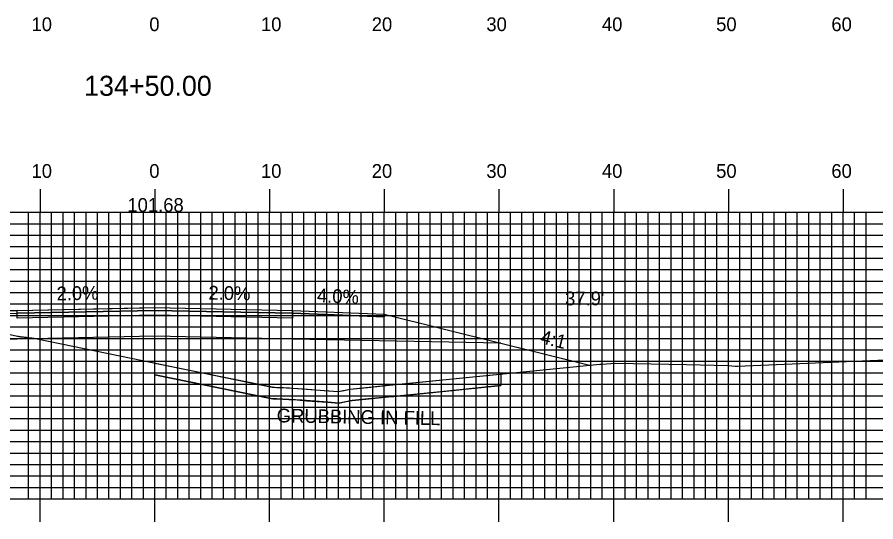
# Model space of a CAD drawing. Extents: x 1774777 to 1775120, y 442591 to 442811.
# Drawn here: x 1774930.7 to 1775005.5, y 442691.7 to 442735.7 of the extents above; entities that cross this region are included whole.
import ezdxf

# ---------------------------------------------------------------- set-up
doc = ezdxf.new("R2010")
doc.units = 0
for name, color, linetype in [('ANNOTATION', 7, 'Continuous'), ('D_Roadway_Centerline', 7, 'Continuous'), ('D_Roadway_Centerline_Text', 7, 'Continuous'), ('D_Roadway_Edge_Shoulder', 7, 'Continuous'), ('D_Roadway_Edge_TW', 7, 'Continuous'), ('D_Roadway_Pavement', 7, 'Continuous'), ('D_Roadway_SlopeLines', 7, 'Continuous'), ('D_Roadway_SubGrade', 7, 'Continuous'), ('D_Text_Standard', 7, 'Continuous'), ('GRUBBING IN FILL', 7, 'Continuous'), ('H_V ANNOTATION', 7, 'Continuous'), ('MAJOR', 7, 'Continuous'), ('MINOR', 7, 'Continuous'), ('S_Roadway_Centerline', 7, 'Continuous')]:
    doc.layers.add(name, color=color, linetype=linetype)

msp = doc.modelspace()

# ---------------------------------------------------------------- linework, layer by layer
at = {"layer": 'D_Roadway_Centerline'}
msp.add_lwpolyline([(1774888.041, 442709.232), (1774889.291, 442709.207), (1774890.427, 442709.137), (1774890.541, 442709.13), (1774890.711, 442709.113), (1774891.791, 442709), (1774892.519, 442708.894), (1774893.041, 442708.818), (1774903.358, 442707.099), (1774908.511, 442706.24), (1774909.434, 442706.471), (1774912.511, 442707.24), (1774916.843, 442708.323), (1774922.685, 442709.784), (1774930.685, 442710.104), (1774941.714, 442710.325), (1774942.685, 442710.344), (1774943.996, 442710.318), (1774954.685, 442710.104), (1774962.685, 442709.784), (1774972.86, 442707.24), (1774975.44, 442706.595), (1774980.561, 442705.315)], dxfattribs=at)
at = {"layer": 'D_Roadway_Edge_Shoulder'}
for points in [[(1774930.685, 442710.104), (1774922.685, 442709.784), (1774922.685, 442709.534), (1774930.685, 442709.854)], [(1774954.685, 442710.104), (1774962.685, 442709.784), (1774962.685, 442709.534), (1774954.685, 442709.854)]]:
    msp.add_lwpolyline(points, close=True, dxfattribs=at)
at = {"layer": 'D_Roadway_Edge_TW'}
msp.add_lwpolyline([(1774930.685, 442709.854), (1774930.685, 442710.104), (1774942.685, 442710.344), (1774954.685, 442710.104), (1774954.685, 442709.854), (1774942.685, 442710.094)], close=True, dxfattribs=at)
at = {"layer": 'D_Roadway_Pavement'}
msp.add_lwpolyline([(1774930.685, 442709.437), (1774930.685, 442709.854), (1774942.685, 442710.094), (1774954.685, 442709.854), (1774954.685, 442709.437), (1774942.685, 442709.677)], close=True, dxfattribs=at)
at = {"layer": 'D_Roadway_SlopeLines'}
msp.add_lwpolyline([(1774962.685, 442709.784), (1774972.86, 442707.24), (1774980.561, 442705.315)], dxfattribs=at)
at = {"layer": 'D_Roadway_SubGrade'}
msp.add_lwpolyline([(1774930.685, 442707.604), (1774912.511, 442707.24), (1774922.685, 442709.784), (1774922.685, 442709.534), (1774930.685, 442709.854), (1774942.685, 442710.094), (1774954.685, 442709.854), (1774962.685, 442709.534), (1774962.685, 442709.784), (1774972.86, 442707.24), (1774954.685, 442707.604), (1774942.685, 442707.844)], close=True, dxfattribs=at)
at = {"layer": 'GRUBBING IN FILL'}
msp.add_line((1774972.86, 442704.545), (1774972.86, 442703.54), dxfattribs=at)
msp.add_line((1774972.86, 442704.545), (1774972.86, 442703.54), dxfattribs=at)
msp.add_lwpolyline([(1774942.685, 442704.493), (1774942.685, 442705.514), (1774953.071, 442703.402), (1774954.719, 442703.319), (1774958.657, 442703.026), (1774959.726, 442703.244), (1774961.501, 442703.422), (1774963.36, 442703.603), (1774972.455, 442704.505), (1774972.86, 442704.545), (1774972.86, 442703.54), (1774968.182, 442703.073), (1774963.505, 442702.606), (1774961.608, 442702.428), (1774959.877, 442702.254), (1774959.048, 442702.085), (1774958.719, 442702.018), (1774957.76, 442702.091), (1774955.513, 442702.26), (1774953.848, 442702.367), (1774952.784, 442702.412)], close=True, dxfattribs=at)
msp.add_lwpolyline([(1774942.685, 442704.493), (1774942.685, 442705.514), (1774953.071, 442703.402), (1774954.719, 442703.319), (1774958.657, 442703.026), (1774959.726, 442703.244), (1774961.501, 442703.422), (1774963.36, 442703.603), (1774972.455, 442704.505), (1774972.86, 442704.545), (1774972.86, 442703.54), (1774968.182, 442703.073), (1774963.505, 442702.606), (1774961.608, 442702.428), (1774959.877, 442702.254), (1774959.048, 442702.085), (1774958.719, 442702.018), (1774957.76, 442702.091), (1774955.513, 442702.26), (1774953.848, 442702.367), (1774952.784, 442702.412)], close=True, dxfattribs=at)
msp.add_lwpolyline([(1774942.685, 442704.493), (1774952.784, 442702.412), (1774952.971, 442702.405), (1774953.094, 442702.4), (1774953.241, 442702.394), (1774953.415, 442702.387), (1774953.617, 442702.378), (1774953.848, 442702.367), (1774954.103, 442702.354), (1774954.367, 442702.339), (1774954.653, 442702.321), (1774955.106, 442702.29), (1774955.92, 442702.23), (1774957.76, 442702.091), (1774958.719, 442702.018), (1774959.376, 442702.151), (1774959.877, 442702.254), (1774963.338, 442702.602), (1774963.505, 442702.606), (1774972.86, 442703.54)], dxfattribs=at)
msp.add_lwpolyline([(1774942.685, 442704.493), (1774952.784, 442702.412), (1774952.971, 442702.405), (1774953.094, 442702.4), (1774953.241, 442702.394), (1774953.415, 442702.387), (1774953.617, 442702.378), (1774953.848, 442702.367), (1774954.103, 442702.354), (1774954.367, 442702.339), (1774954.653, 442702.321), (1774955.106, 442702.29), (1774955.92, 442702.23), (1774957.76, 442702.091), (1774958.719, 442702.018), (1774959.376, 442702.151), (1774959.877, 442702.254), (1774963.338, 442702.602), (1774963.505, 442702.606), (1774972.86, 442703.54)], dxfattribs=at)
at = {"layer": 'MAJOR'}
for p, q in [((1774932.685, 442720.669), (1774932.685, 442718.665)), ((1774942.685, 442720.669), (1774942.685, 442718.665)), ((1774952.685, 442720.669), (1774952.685, 442718.665)), ((1774962.685, 442720.669), (1774962.685, 442718.665)), ((1774972.685, 442720.669), (1774972.685, 442718.665)), ((1774982.685, 442720.669), (1774982.685, 442718.665)), ((1774992.685, 442720.669), (1774992.685, 442718.665)), ((1775002.685, 442720.669), (1775002.685, 442718.665)), ((1774802.685, 442718.665), (1775082.685, 442718.665)), ((1774802.685, 442718.665), (1775082.685, 442718.665)), ((1774932.685, 442693.665), (1774932.685, 442718.665)), ((1774942.685, 442693.665), (1774942.685, 442718.665)), ((1774952.685, 442693.665), (1774952.685, 442718.665)), ((1774962.685, 442693.665), (1774962.685, 442718.665)), ((1774972.685, 442693.665), (1774972.685, 442718.665)), ((1774982.685, 442693.665), (1774982.685, 442718.665)), ((1774992.685, 442693.665), (1774992.685, 442718.665)), ((1775002.685, 442693.665), (1775002.685, 442718.665)), ((1774802.685, 442713.665), (1775082.685, 442713.665)), ((1774802.685, 442708.665), (1775082.685, 442708.665)), ((1774802.685, 442703.665), (1775082.685, 442703.665)), ((1774802.685, 442698.665), (1775082.685, 442698.665)), ((1774802.685, 442693.665), (1775082.685, 442693.665)), ((1774802.685, 442693.665), (1775082.685, 442693.665)), ((1774932.685, 442691.661), (1774932.685, 442693.665)), ((1774942.685, 442691.661), (1774942.685, 442693.665)), ((1774952.685, 442691.661), (1774952.685, 442693.665)), ((1774962.685, 442691.661), (1774962.685, 442693.665)), ((1774972.685, 442691.661), (1774972.685, 442693.665)), ((1774982.685, 442691.661), (1774982.685, 442693.665)), ((1774992.685, 442691.661), (1774992.685, 442693.665)), ((1775002.685, 442691.661), (1775002.685, 442693.665))]:
    msp.add_line(p, q, dxfattribs=at)
at = {"layer": 'MINOR'}
for p, q in [((1774931.685, 442693.665), (1774931.685, 442718.665)), ((1774933.685, 442693.665), (1774933.685, 442718.665)), ((1774934.685, 442693.665), (1774934.685, 442718.665)), ((1774935.685, 442693.665), (1774935.685, 442718.665)), ((1774936.685, 442693.665), (1774936.685, 442718.665)), ((1774937.685, 442693.665), (1774937.685, 442718.665)), ((1774938.685, 442693.665), (1774938.685, 442718.665)), ((1774939.685, 442693.665), (1774939.685, 442718.665)), ((1774940.685, 442693.665), (1774940.685, 442718.665)), ((1774941.685, 442693.665), (1774941.685, 442718.665)), ((1774943.685, 442693.665), (1774943.685, 442718.665)), ((1774944.685, 442693.665), (1774944.685, 442718.665)), ((1774945.685, 442693.665), (1774945.685, 442718.665)), ((1774946.685, 442693.665), (1774946.685, 442718.665)), ((1774947.685, 442693.665), (1774947.685, 442718.665)), ((1774948.685, 442693.665), (1774948.685, 442718.665)), ((1774949.685, 442693.665), (1774949.685, 442718.665)), ((1774950.685, 442693.665), (1774950.685, 442718.665)), ((1774951.685, 442693.665), (1774951.685, 442718.665)), ((1774953.685, 442693.665), (1774953.685, 442718.665)), ((1774954.685, 442693.665), (1774954.685, 442718.665)), ((1774955.685, 442693.665), (1774955.685, 442718.665)), ((1774956.685, 442693.665), (1774956.685, 442718.665)), ((1774957.685, 442693.665), (1774957.685, 442718.665)), ((1774958.685, 442693.665), (1774958.685, 442718.665)), ((1774959.685, 442693.665), (1774959.685, 442718.665)), ((1774960.685, 442693.665), (1774960.685, 442718.665)), ((1774961.685, 442693.665), (1774961.685, 442718.665)), ((1774963.685, 442693.665), (1774963.685, 442718.665)), ((1774964.685, 442693.665), (1774964.685, 442718.665)), ((1774965.685, 442693.665), (1774965.685, 442718.665)), ((1774966.685, 442693.665), (1774966.685, 442718.665)), ((1774967.685, 442693.665), (1774967.685, 442718.665)), ((1774968.685, 442693.665), (1774968.685, 442718.665)), ((1774969.685, 442693.665), (1774969.685, 442718.665)), ((1774970.685, 442693.665), (1774970.685, 442718.665)), ((1774971.685, 442693.665), (1774971.685, 442718.665)), ((1774973.685, 442693.665), (1774973.685, 442718.665)), ((1774974.685, 442693.665), (1774974.685, 442718.665)), ((1774975.685, 442693.665), (1774975.685, 442718.665)), ((1774976.685, 442693.665), (1774976.685, 442718.665)), ((1774977.685, 442693.665), (1774977.685, 442718.665)), ((1774978.685, 442693.665), (1774978.685, 442718.665)), ((1774979.685, 442693.665), (1774979.685, 442718.665)), ((1774980.685, 442693.665), (1774980.685, 442718.665)), ((1774981.685, 442693.665), (1774981.685, 442718.665)), ((1774983.685, 442693.665), (1774983.685, 442718.665)), ((1774984.685, 442693.665), (1774984.685, 442718.665)), ((1774985.685, 442693.665), (1774985.685, 442718.665)), ((1774986.685, 442693.665), (1774986.685, 442718.665)), ((1774987.685, 442693.665), (1774987.685, 442718.665)), ((1774988.685, 442693.665), (1774988.685, 442718.665)), ((1774989.685, 442693.665), (1774989.685, 442718.665)), ((1774990.685, 442693.665), (1774990.685, 442718.665)), ((1774991.685, 442693.665), (1774991.685, 442718.665)), ((1774993.685, 442693.665), (1774993.685, 442718.665)), ((1774994.685, 442693.665), (1774994.685, 442718.665)), ((1774995.685, 442693.665), (1774995.685, 442718.665)), ((1774996.685, 442693.665), (1774996.685, 442718.665)), ((1774997.685, 442693.665), (1774997.685, 442718.665)), ((1774998.685, 442693.665), (1774998.685, 442718.665)), ((1774999.685, 442693.665), (1774999.685, 442718.665)), ((1775000.685, 442693.665), (1775000.685, 442718.665)), ((1775001.685, 442693.665), (1775001.685, 442718.665)), ((1775003.685, 442693.665), (1775003.685, 442718.665)), ((1775004.685, 442693.665), (1775004.685, 442718.665)), ((1774802.685, 442717.665), (1775082.685, 442717.665)), ((1774802.685, 442716.665), (1775082.685, 442716.665)), ((1774802.685, 442715.665), (1775082.685, 442715.665)), ((1774802.685, 442714.665), (1775082.685, 442714.665)), ((1774802.685, 442712.665), (1775082.685, 442712.665)), ((1774802.685, 442711.665), (1775082.685, 442711.665)), ((1774802.685, 442710.665), (1775082.685, 442710.665)), ((1774802.685, 442709.665), (1775082.685, 442709.665)), ((1774802.685, 442707.665), (1775082.685, 442707.665)), ((1774802.685, 442706.665), (1775082.685, 442706.665)), ((1774802.685, 442705.665), (1775082.685, 442705.665)), ((1774802.685, 442704.665), (1775082.685, 442704.665)), ((1774802.685, 442702.665), (1775082.685, 442702.665)), ((1774802.685, 442701.665), (1775082.685, 442701.665)), ((1774802.685, 442700.665), (1775082.685, 442700.665)), ((1774802.685, 442699.665), (1775082.685, 442699.665)), ((1774802.685, 442697.665), (1775082.685, 442697.665)), ((1774802.685, 442696.665), (1775082.685, 442696.665)), ((1774802.685, 442695.665), (1775082.685, 442695.665)), ((1774802.685, 442694.665), (1775082.685, 442694.665))]:
    msp.add_line(p, q, dxfattribs=at)
at = {"layer": 'S_Roadway_Centerline'}
msp.add_lwpolyline([(1774929.819, 442708.068), (1774930.727, 442707.854), (1774930.778, 442707.845), (1774930.829, 442707.836), (1774930.877, 442707.828), (1774930.921, 442707.821), (1774930.96, 442707.815), (1774931.008, 442707.809), (1774931.068, 442707.802), (1774931.137, 442707.795), (1774931.214, 442707.787), (1774931.297, 442707.778), (1774931.386, 442707.769), (1774931.477, 442707.759), (1774931.569, 442707.75), (1774931.967, 442707.698), (1774932.167, 442707.668), (1774932.419, 442707.63), (1774952.904, 442703.408), (1774953.009, 442703.404), (1774953.134, 442703.399), (1774953.283, 442703.393), (1774953.458, 442703.386), (1774953.663, 442703.377), (1774953.897, 442703.366), (1774954.156, 442703.353), (1774954.426, 442703.338), (1774954.719, 442703.319), (1774955.178, 442703.287), (1774955.994, 442703.227), (1774957.835, 442703.088), (1774958.657, 442703.026), (1774959.176, 442703.131), (1774959.726, 442703.244), (1774963.277, 442703.601), (1774963.444, 442703.605), (1774981.467, 442705.405), (1774981.69, 442705.421), (1774982.046, 442705.447), (1774982.443, 442705.475), (1774982.859, 442705.506), (1774989.029, 442705.387), (1774992.668, 442705.311), (1774992.99, 442705.277), (1774993.272, 442705.249), (1774993.361, 442705.242), (1774993.465, 442705.235), (1775011.134, 442706.004)], dxfattribs=at)

# ---------------------------------------------------------------- texts
at = {"layer": 'ANNOTATION'}
for s, rotation, p in [('2.0%', 1.14576, (1774934.127, 442710.973)), ('2.0%', 358.85418, (1774947.347, 442711.051)), ('4.0%', 357.70947, (1774956.797, 442710.821)), ('4:1', 345.96569, (1774976.216, 442707.263))]:
    msp.add_text(s, height=1.2, rotation=rotation, dxfattribs=at).set_placement(p)
at = {"layer": 'D_Roadway_Centerline'}
for s, p in [('C', (1774942.68, 442710.344)), ('L', (1774942.685, 442710.337))]:
    msp.add_text(s, height=0.0146, dxfattribs=at).set_placement(p)
at = {"layer": 'D_Roadway_Centerline_Text'}
msp.add_text('101.68', height=1.2, dxfattribs=at).set_placement((1774940.294, 442718.699))
at = {"layer": 'D_Text_Standard'}
msp.add_text("37.9'", height=1.2, dxfattribs=at).set_placement((1774978.448, 442710.547))
at = {"layer": 'GRUBBING IN FILL'}
msp.add_text('GRUBBING IN FILL', height=1.2, rotation=358.9728, dxfattribs=at).set_placement((1774953.302, 442700.345))
at = {"layer": 'H_V ANNOTATION'}
for s, height, p in [('10', 1.2, (1774931.936, 442734.465)), ('0', 1.2, (1774942.203, 442734.465)), ('10', 1.2, (1774951.936, 442734.465)), ('20', 1.2, (1774961.593, 442734.465)), ('30', 1.2, (1774971.583, 442734.465)), ('40', 1.2, (1774981.657, 442734.465)), ('50', 1.2, (1774991.614, 442734.465)), ('60', 1.2, (1775001.657, 442734.465)), ('134+50.00', 1.75, (1774936.521, 442728.821)), ('10', 1.2, (1774931.936, 442721.665)), ('0', 1.2, (1774942.203, 442721.665)), ('10', 1.2, (1774951.936, 442721.665)), ('20', 1.2, (1774961.593, 442721.665)), ('30', 1.2, (1774971.583, 442721.665)), ('40', 1.2, (1774981.657, 442721.665)), ('50', 1.2, (1774991.614, 442721.665)), ('60', 1.2, (1775001.657, 442721.665))]:
    msp.add_text(s, height=height, dxfattribs=at).set_placement(p)

doc.saveas('drawing.dxf')
